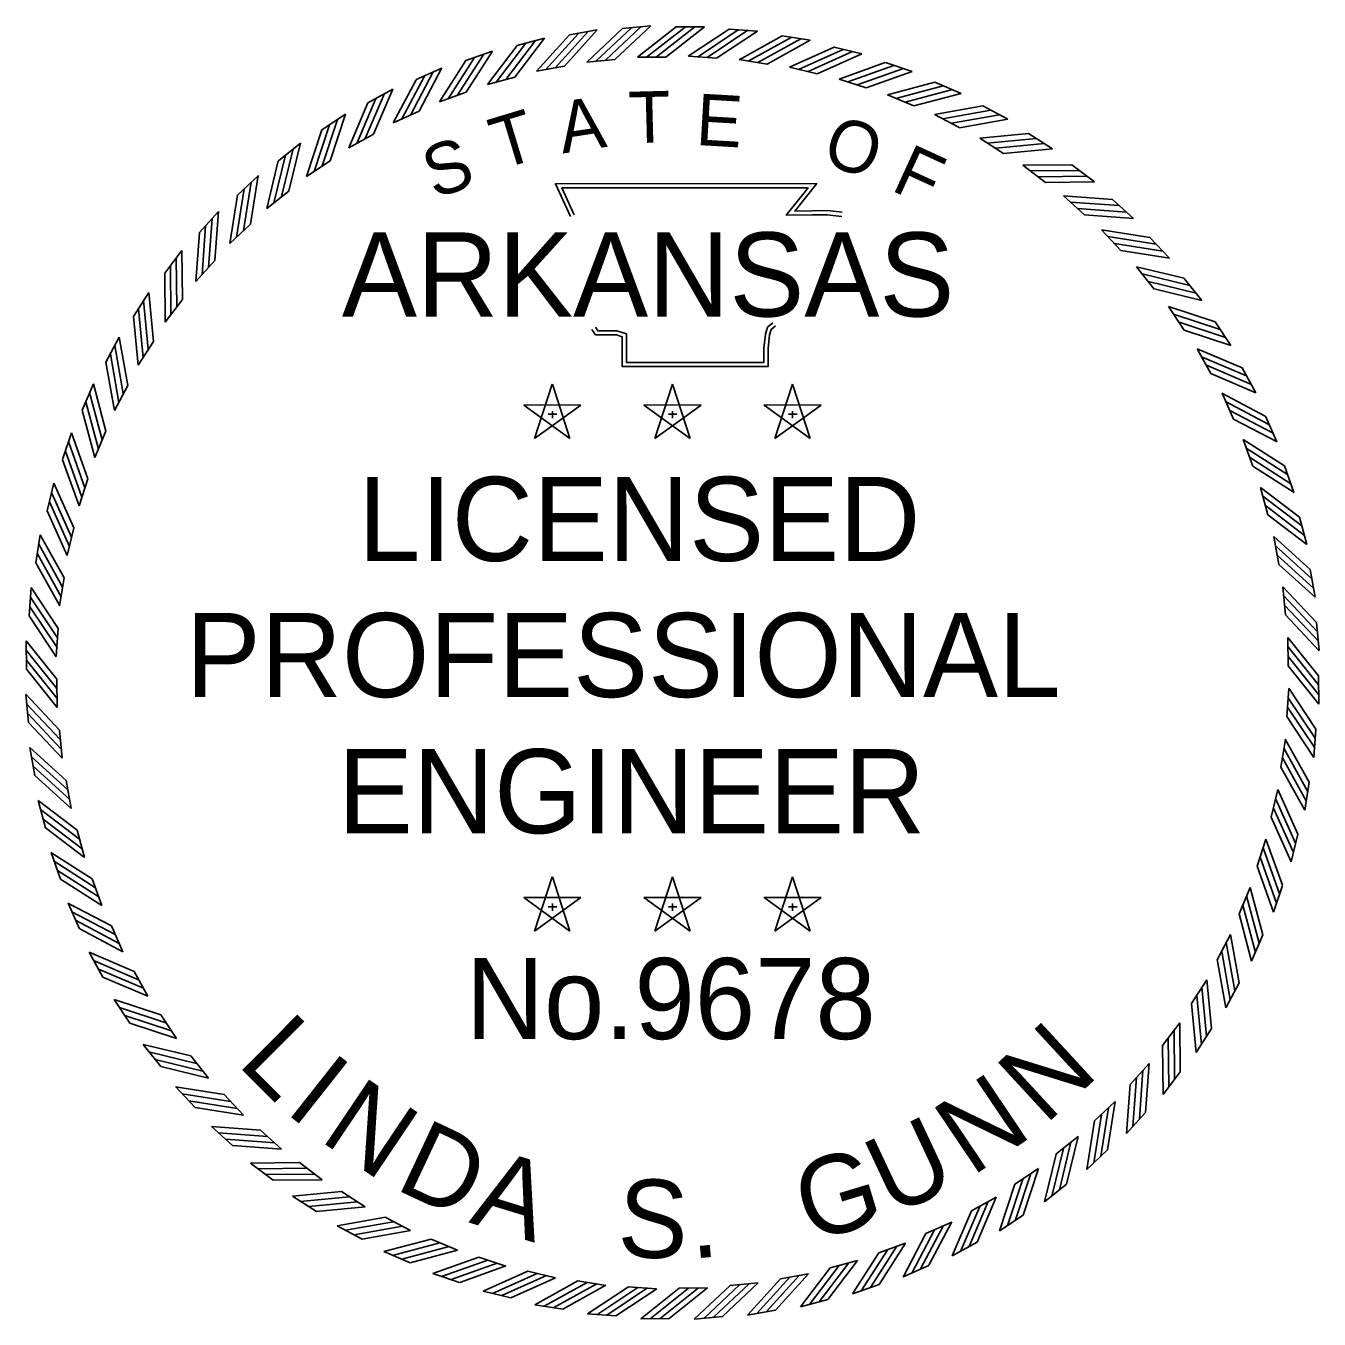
# Model space of a CAD drawing. Extents: x -160 to 6143532, y -375 to 762199.
# Drawn here: x 566 to 597.06, y -166.74 to -135.68 of the extents above; entities that cross this region are included whole.
import ezdxf

# ---------------------------------------------------------------- set-up
doc = ezdxf.new("R2010")
doc.units = 0
doc.layers.add('STAMP', color=7, linetype='Continuous')

msp = doc.modelspace()

# ---------------------------------------------------------------- linework, layer by layer
at = {"layer": 'STAMP'}
for p, q in [((580.329, -135.745), (581.006, -135.682)), ((581.617, -135.707), (582.297, -135.707)), ((577.8, -136.153), (578.458, -135.98)), ((579.056, -135.897), (579.726, -135.779)), ((582.891, -135.758), (583.569, -135.808)), ((584.162, -135.923), (584.834, -136.029)), ((576.57, -136.513), (577.211, -136.286)), ((585.415, -136.192), (586.076, -136.353)), ((579.471, -136.55), (580.15, -136.488)), ((580.689, -136.43), (581.37, -136.43)), ((581.912, -136.411), (582.592, -136.461)), ((583.133, -136.493), (583.806, -136.599)), ((586.642, -136.564), (587.288, -136.779)), ((575.373, -136.973), (575.993, -136.694)), ((577.087, -137.089), (577.746, -136.916)), ((578.268, -136.771), (578.939, -136.652)), ((584.343, -136.676), (585.005, -136.837)), ((574.218, -137.53), (574.813, -137.201)), ((585.533, -136.958), (586.18, -137.173)), ((587.834, -137.036), (588.459, -137.304)), ((575.936, -137.505), (576.578, -137.277)), ((586.696, -137.337), (587.323, -137.605)), ((573.114, -138.181), (573.68, -137.803)), ((574.823, -138.014), (575.445, -137.734)), ((587.824, -137.811), (588.427, -138.13)), ((588.983, -137.605), (589.584, -137.924)), ((572.067, -138.92), (572.599, -138.498)), ((573.756, -138.613), (574.353, -138.283)), ((588.909, -138.376), (589.483, -138.744)), ((590.081, -138.267), (590.654, -138.634)), ((572.743, -139.298), (573.31, -138.919)), ((589.944, -139.029), (590.485, -139.443)), ((591.121, -139.017), (591.661, -139.43)), ((571.084, -139.744), (571.58, -139.279)), ((571.789, -140.064), (572.323, -139.64)), ((590.921, -139.766), (591.426, -140.223)), ((592.095, -139.851), (592.599, -140.307)), ((570.173, -140.646), (570.629, -140.141)), ((570.902, -140.907), (571.399, -140.44)), ((591.834, -140.58), (592.3, -141.077)), ((592.996, -140.762), (593.462, -141.258)), ((569.339, -141.62), (569.752, -141.079)), ((570.088, -141.819), (570.545, -141.314)), ((592.676, -141.467), (593.1, -142.001)), ((593.82, -141.745), (594.243, -142.277)), ((568.589, -142.659), (568.956, -142.086)), ((569.351, -142.797), (569.765, -142.255)), ((593.443, -142.421), (593.821, -142.988)), ((594.56, -142.792), (594.937, -143.358)), ((567.927, -143.757), (568.245, -143.156)), ((568.698, -143.831), (569.066, -143.257)), ((594.128, -143.435), (594.458, -144.031)), ((595.21, -143.896), (595.539, -144.491)), ((567.358, -144.906), (567.626, -144.281)), ((568.133, -144.916), (568.452, -144.314)), ((578.645, -144.288), (578.219, -145.593)), ((579.069, -145.592), (578.646, -144.286)), ((581.53, -144.288), (581.104, -145.593)), ((581.954, -145.592), (581.531, -144.286)), ((584.415, -144.288), (583.989, -145.593)), ((584.838, -145.592), (584.415, -144.286)), ((594.727, -144.501), (595.006, -145.123)), ((579.331, -144.786), (577.958, -144.785)), ((577.959, -144.786), (579.069, -145.594)), ((578.221, -145.592), (579.333, -144.786)), ((578.547, -145.005), (578.751, -145.005)), ((578.646, -144.932), (578.646, -145.104)), ((582.216, -144.786), (580.843, -144.785)), ((580.844, -144.786), (581.954, -145.594)), ((581.106, -145.592), (582.217, -144.786)), ((581.432, -145.005), (581.636, -145.005)), ((581.531, -144.932), (581.531, -145.104)), ((585.1, -144.786), (583.727, -144.785)), ((583.729, -144.786), (584.839, -145.594)), ((583.991, -145.592), (585.102, -144.786)), ((584.317, -145.005), (584.521, -145.005)), ((584.416, -144.932), (584.416, -145.104)), ((595.767, -145.051), (596.046, -145.671)), ((566.886, -146.098), (567.101, -145.453)), ((567.659, -146.044), (567.927, -145.417)), ((595.236, -145.614), (595.463, -146.257)), ((596.227, -146.248), (596.454, -146.889)), ((567.28, -147.207), (567.495, -146.56)), ((566.514, -147.325), (566.675, -146.664)), ((595.651, -146.765), (595.824, -147.424)), ((596.587, -147.478), (596.76, -148.136)), ((566.998, -148.398), (567.159, -147.735)), ((566.245, -148.578), (566.35, -147.906)), ((595.97, -147.946), (596.088, -148.617)), ((596.843, -148.734), (596.962, -149.404)), ((566.815, -149.607), (566.921, -148.934)), ((566.08, -149.849), (566.13, -149.171)), ((596.19, -149.149), (596.252, -149.828)), ((566.733, -150.828), (566.783, -150.148)), ((596.996, -150.007), (597.058, -150.684)), ((566.02, -151.13), (566.014, -150.45)), ((596.31, -150.367), (596.316, -151.049)), ((566.752, -152.051), (566.746, -151.37)), ((597.042, -151.288), (597.048, -151.968)), ((566.067, -152.411), (566.004, -151.734)), ((596.329, -151.59), (596.279, -152.27)), ((566.872, -153.269), (566.81, -152.59)), ((596.982, -152.569), (596.933, -153.247)), ((566.219, -153.684), (566.101, -153.014)), ((596.247, -152.811), (596.141, -153.484)), ((567.093, -154.472), (566.974, -153.801)), ((596.064, -154.021), (595.903, -154.683)), ((596.817, -153.84), (596.712, -154.512)), ((566.475, -154.94), (566.302, -154.282)), ((567.411, -155.654), (567.238, -154.994)), ((595.782, -155.211), (595.567, -155.858)), ((596.548, -155.094), (596.387, -155.754)), ((566.835, -156.171), (566.608, -155.529)), ((567.827, -156.804), (567.599, -156.162)), ((578.645, -156.116), (578.219, -157.421)), ((579.069, -157.42), (578.646, -156.114)), ((581.53, -156.116), (581.104, -157.421)), ((581.954, -157.42), (581.531, -156.114)), ((584.415, -156.116), (583.989, -157.421)), ((584.838, -157.42), (584.415, -156.114)), ((595.403, -156.374), (595.135, -157.001)), ((596.176, -156.32), (595.961, -156.966)), ((567.295, -157.367), (567.016, -156.747)), ((579.331, -156.614), (577.958, -156.613)), ((577.959, -156.614), (579.069, -157.422)), ((578.221, -157.42), (579.333, -156.614)), ((578.646, -156.76), (578.646, -156.932)), ((582.216, -156.614), (580.843, -156.613)), ((580.844, -156.614), (581.954, -157.422)), ((581.106, -157.42), (582.217, -156.614)), ((581.531, -156.76), (581.531, -156.932)), ((585.1, -156.614), (583.727, -156.613)), ((583.729, -156.614), (584.839, -157.422)), ((583.991, -157.42), (585.102, -156.614)), ((584.416, -156.76), (584.416, -156.932)), ((578.547, -156.833), (578.751, -156.833)), ((581.432, -156.833), (581.636, -156.833)), ((584.317, -156.833), (584.521, -156.833)), ((568.335, -157.917), (568.056, -157.295)), ((594.929, -157.502), (594.61, -158.105)), ((595.704, -157.512), (595.436, -158.138)), ((567.852, -158.522), (567.523, -157.927)), ((568.934, -158.984), (568.604, -158.387)), ((594.364, -158.587), (593.996, -159.161)), ((595.135, -158.661), (594.817, -159.262)), ((568.503, -159.627), (568.125, -159.061)), ((569.619, -159.997), (569.241, -159.43)), ((593.711, -159.622), (593.297, -160.164)), ((594.473, -159.759), (594.106, -160.332)), ((569.242, -160.674), (568.82, -160.141)), ((570.386, -160.951), (569.962, -160.417)), ((592.975, -160.599), (592.517, -161.105)), ((593.723, -160.799), (593.31, -161.339)), ((570.066, -161.656), (569.601, -161.16)), ((571.228, -161.838), (570.762, -161.341)), ((592.16, -161.512), (591.663, -161.978)), ((592.889, -161.773), (592.433, -162.277)), ((570.968, -162.567), (570.463, -162.111)), ((572.141, -162.653), (571.636, -162.196)), ((591.273, -162.354), (590.739, -162.778)), ((591.978, -162.675), (591.482, -163.14)), ((571.942, -163.401), (571.401, -162.988)), ((573.118, -163.389), (572.577, -162.975)), ((590.319, -163.121), (589.752, -163.499)), ((590.996, -163.498), (590.463, -163.921)), ((572.981, -164.151), (572.408, -163.784)), ((574.153, -164.042), (573.579, -163.674)), ((589.306, -163.806), (588.709, -164.136)), ((589.948, -164.238), (589.383, -164.615)), ((574.079, -164.813), (573.478, -164.495)), ((575.238, -164.607), (574.635, -164.289)), ((588.239, -164.405), (587.617, -164.684)), ((576.366, -165.081), (575.739, -164.813)), ((588.844, -164.888), (588.249, -165.217)), ((575.228, -165.382), (574.603, -165.114)), ((587.126, -164.914), (586.484, -165.141)), ((577.529, -165.461), (576.882, -165.245)), ((585.975, -165.329), (585.316, -165.502)), ((587.689, -165.445), (587.069, -165.724)), ((576.42, -165.854), (575.775, -165.639)), ((578.72, -165.742), (578.057, -165.581)), ((579.929, -165.925), (579.256, -165.819)), ((584.794, -165.648), (584.123, -165.766)), ((577.647, -166.226), (576.986, -166.065)), ((581.15, -166.007), (580.47, -165.957)), ((582.373, -165.988), (581.692, -165.994)), ((583.591, -165.868), (582.912, -165.93)), ((586.493, -165.905), (585.851, -166.132)), ((578.9, -166.495), (578.228, -166.39)), ((585.262, -166.265), (584.604, -166.438)), ((580.171, -166.661), (579.493, -166.611)), ((581.452, -166.72), (580.772, -166.726)), ((582.733, -166.674), (582.056, -166.736)), ((584.006, -166.522), (583.336, -166.64))]:
    msp.add_line(p, q, dxfattribs=at)
for points in [[(579.923, -136.506), (580.781, -135.7)], [(580.149, -136.488), (581.007, -135.682)], [(580.688, -136.431), (581.616, -135.707)], [(580.907, -136.433), (581.835, -135.709)], [(581.143, -136.428), (582.071, -135.704)], [(581.37, -136.43), (582.298, -135.706)], [(577.745, -136.916), (578.458, -135.98)], [(578.267, -136.771), (579.055, -135.898)], [(578.483, -136.735), (579.271, -135.862)], [(578.715, -136.689), (579.503, -135.815)], [(578.938, -136.652), (579.726, -135.778)], [(579.471, -136.551), (580.328, -135.745)], [(579.689, -136.533), (580.546, -135.727)], [(581.911, -136.412), (582.89, -135.758)], [(582.129, -136.43), (583.108, -135.776)], [(582.365, -136.442), (583.344, -135.789)], [(582.591, -136.461), (583.57, -135.807)], [(583.132, -136.494), (584.161, -135.923)], [(583.348, -136.53), (584.377, -135.959)], [(583.582, -136.561), (584.611, -135.991)], [(576.578, -137.277), (577.211, -136.286)], [(577.086, -137.09), (577.799, -136.154)], [(577.298, -137.037), (578.011, -136.101)], [(577.525, -136.971), (578.239, -136.035)], [(583.805, -136.599), (584.835, -136.028)], [(584.342, -136.676), (585.414, -136.193)], [(584.554, -136.73), (585.627, -136.246)], [(584.785, -136.781), (585.857, -136.297)], [(575.935, -137.506), (576.569, -136.514)], [(576.142, -137.434), (576.776, -136.443)], [(576.363, -137.351), (576.997, -136.359)], [(585.004, -136.837), (586.077, -136.353)], [(585.532, -136.958), (586.641, -136.565)], [(585.739, -137.029), (586.848, -136.636)], [(575.023, -137.927), (575.573, -136.886)], [(575.237, -137.825), (575.786, -136.784)], [(575.444, -137.734), (575.994, -136.693)], [(585.965, -137.099), (587.074, -136.705)], [(586.179, -137.172), (587.288, -136.779)], [(574.352, -138.283), (574.814, -137.2)], [(574.823, -138.014), (575.372, -136.974)], [(586.695, -137.337), (587.833, -137.037)], [(586.896, -137.425), (588.034, -137.125)], [(587.115, -137.513), (588.253, -137.213)], [(573.756, -138.613), (574.218, -137.531)], [(573.949, -138.509), (574.41, -137.427)], [(574.153, -138.39), (574.614, -137.308)], [(587.323, -137.604), (588.46, -137.304)], [(573.309, -138.92), (573.68, -137.803)], [(587.823, -137.811), (588.982, -137.605)], [(588.016, -137.915), (589.174, -137.71)], [(588.227, -138.021), (589.386, -137.816)], [(572.742, -139.299), (573.113, -138.182)], [(572.926, -139.179), (573.296, -138.062)], [(573.119, -139.043), (573.49, -137.927)], [(588.426, -138.129), (589.585, -137.923)], [(572.322, -139.64), (572.6, -138.497)], [(588.908, -138.376), (590.08, -138.267)], [(589.091, -138.496), (590.263, -138.387)], [(571.962, -139.931), (572.239, -138.787)], [(572.143, -139.78), (572.421, -138.636)], [(589.293, -138.619), (590.465, -138.51)], [(589.483, -138.743), (590.655, -138.634)], [(571.789, -140.065), (572.066, -138.921)], [(589.943, -139.029), (591.119, -139.017)], [(571.232, -140.594), (571.414, -139.431)], [(571.398, -140.44), (571.58, -139.278)], [(590.115, -139.164), (591.292, -139.152)], [(590.306, -139.303), (591.483, -139.291)], [(590.485, -139.442), (591.662, -139.43)], [(570.902, -140.908), (571.084, -139.745)], [(571.063, -140.759), (571.245, -139.597)], [(579.083, -140.259), (578.721, -139.473), (584.993, -139.47), (584.469, -140.128), (584.895, -140.123), (585.251, -140.118), (585.606, -140.157)], [(579.173, -140.217), (578.876, -139.573), (584.787, -139.569), (584.261, -140.23), (584.896, -140.222), (585.246, -140.217), (585.596, -140.256)], [(590.92, -139.766), (592.093, -139.851)], [(591.081, -139.914), (592.254, -139.999)], [(570.39, -141.481), (570.476, -140.307)], [(570.544, -141.314), (570.629, -140.14)], [(591.26, -140.068), (592.433, -140.154)], [(591.426, -140.222), (592.6, -140.307)], [(570.088, -141.82), (570.173, -140.647)], [(570.236, -141.659), (570.321, -140.486)], [(591.833, -140.58), (592.995, -140.762)], [(591.981, -140.741), (593.144, -140.923)], [(592.146, -140.91), (593.309, -141.092)], [(569.625, -142.434), (569.613, -141.257)], [(569.764, -142.255), (569.752, -141.078)], [(592.3, -141.076), (593.462, -141.258)], [(569.486, -142.625), (569.474, -141.448)], [(592.675, -141.467), (593.819, -141.744)], [(569.351, -142.798), (569.339, -141.621)], [(592.81, -141.64), (593.953, -141.917)], [(592.961, -141.822), (594.104, -142.099)], [(569.065, -143.257), (568.956, -142.086)], [(593.1, -142), (594.243, -142.278)], [(568.818, -143.649), (568.709, -142.477)], [(568.941, -143.447), (568.832, -142.275)], [(593.442, -142.421), (594.558, -142.791)], [(568.698, -143.832), (568.589, -142.66)], [(583.942, -142.81), (583.81, -142.917), (583.764, -143.086), (583.727, -143.424), (583.727, -143.764), (580.424, -143.764), (580.424, -143.278), (580.424, -143.074), (580.198, -143.005), (579.739, -143.005), (579.68, -142.915)], [(593.561, -142.604), (594.678, -142.975)], [(593.697, -142.797), (594.814, -143.168)], [(568.451, -144.314), (568.245, -143.155)], [(584.004, -142.887), (583.898, -142.974), (583.862, -143.104), (583.827, -143.429), (583.827, -143.863), (580.325, -143.863), (580.325, -143.278), (580.325, -143.148), (580.183, -143.104), (579.685, -143.104), (579.597, -142.969)], [(593.821, -142.987), (594.938, -143.358)], [(568.343, -144.513), (568.137, -143.355)], [(594.127, -143.434), (595.209, -143.896)], [(568.133, -144.917), (567.927, -143.758)], [(568.237, -144.724), (568.032, -143.566)], [(594.231, -143.627), (595.313, -144.088)], [(594.35, -143.831), (595.432, -144.293)], [(594.458, -144.03), (595.54, -144.492)], [(567.926, -145.418), (567.626, -144.28)], [(567.747, -145.844), (567.447, -144.707)], [(567.835, -145.625), (567.535, -144.487)], [(594.726, -144.501), (595.766, -145.05)], [(594.814, -144.701), (595.854, -145.251)], [(567.659, -146.045), (567.359, -144.907)], [(594.915, -144.915), (595.956, -145.464)], [(595.006, -145.122), (596.047, -145.672)], [(567.494, -146.561), (567.101, -145.452)], [(595.235, -145.613), (596.226, -146.247)], [(567.351, -147.001), (566.958, -145.892)], [(567.421, -146.775), (567.027, -145.666)], [(595.306, -145.82), (596.297, -146.454)], [(567.28, -147.208), (566.887, -146.099)], [(595.389, -146.041), (596.381, -146.675)], [(595.463, -146.256), (596.455, -146.889)], [(567.103, -147.956), (566.619, -146.883)], [(567.158, -147.736), (566.675, -146.663)], [(595.65, -146.764), (596.586, -147.477)], [(567.052, -148.186), (566.568, -147.114)], [(595.704, -146.976), (596.64, -147.69)], [(566.998, -148.399), (566.515, -147.326)], [(595.769, -147.203), (596.705, -147.917)], [(595.824, -147.423), (596.76, -148.136)], [(566.883, -149.158), (566.313, -148.129)], [(566.921, -148.935), (566.35, -147.906)], [(595.969, -147.945), (596.843, -148.733)], [(566.852, -149.392), (566.281, -148.363)], [(596.005, -148.161), (596.879, -148.949)], [(596.051, -148.393), (596.925, -149.181)], [(566.816, -149.608), (566.245, -148.579)], [(596.088, -148.616), (596.962, -149.404)], [(566.783, -150.149), (566.129, -149.17)], [(596.189, -149.149), (596.995, -150.006)], [(596.207, -149.367), (597.013, -150.224)], [(566.752, -150.611), (566.098, -149.632)], [(566.764, -150.375), (566.11, -149.396)], [(596.234, -149.602), (597.04, -150.459)], [(566.734, -150.829), (566.08, -149.85)], [(596.253, -149.827), (597.058, -150.685)], [(566.746, -151.371), (566.013, -150.449)], [(596.309, -150.366), (597.041, -151.287)], [(596.309, -150.585), (597.041, -151.506)], [(566.746, -151.597), (566.013, -150.676)], [(566.753, -151.833), (566.021, -150.912)], [(596.317, -150.821), (597.049, -151.742)], [(566.753, -152.052), (566.021, -151.131)], [(596.317, -151.048), (597.049, -151.969)], [(566.809, -152.591), (566.004, -151.733)], [(596.31, -151.807), (596.964, -152.786)], [(596.328, -151.589), (596.982, -152.568)], [(566.828, -152.817), (566.022, -151.959)], [(596.298, -152.043), (596.952, -153.022)], [(566.855, -153.052), (566.049, -152.194)], [(566.873, -153.27), (566.067, -152.412)], [(596.279, -152.269), (596.933, -153.248)], [(566.974, -153.802), (566.1, -153.014)], [(596.21, -153.026), (596.781, -154.055)], [(596.246, -152.81), (596.817, -153.839)], [(567.011, -154.025), (566.137, -153.237)], [(596.179, -153.26), (596.749, -154.289)], [(567.057, -154.257), (566.183, -153.469)], [(567.093, -154.473), (566.219, -153.685)], [(596.141, -153.484), (596.712, -154.513)], [(596.064, -154.02), (596.548, -155.092)], [(567.238, -154.995), (566.302, -154.282)], [(596.01, -154.232), (596.494, -155.305)], [(567.293, -155.215), (566.357, -154.502)], [(595.959, -154.463), (596.443, -155.535)], [(567.358, -155.442), (566.422, -154.729)], [(567.412, -155.654), (566.476, -154.941)], [(595.904, -154.682), (596.387, -155.755)], [(595.782, -155.21), (596.176, -156.319)], [(567.599, -156.163), (566.607, -155.529)], [(595.711, -155.417), (596.104, -156.526)], [(567.673, -156.377), (566.681, -155.743)], [(595.568, -155.857), (595.961, -156.966)], [(595.641, -155.643), (596.035, -156.752)], [(567.756, -156.598), (566.765, -155.964)], [(567.827, -156.805), (566.836, -156.171)], [(595.403, -156.373), (595.704, -157.511)], [(568.056, -157.296), (567.015, -156.747)], [(595.227, -156.793), (595.528, -157.931)], [(595.315, -156.574), (595.616, -157.712)], [(568.147, -157.504), (567.106, -156.954)], [(595.136, -157.001), (595.436, -158.138)], [(568.248, -157.717), (567.208, -157.167)], [(568.336, -157.917), (567.296, -157.368)], [(594.825, -157.694), (595.031, -158.852)], [(594.929, -157.501), (595.135, -158.66)], [(568.604, -158.388), (567.522, -157.926)], [(594.719, -157.905), (594.925, -159.064)], [(568.712, -158.587), (567.63, -158.126)], [(568.831, -158.792), (567.749, -158.33)], [(594.611, -158.104), (594.817, -159.263)], [(568.935, -158.984), (567.853, -158.522)], [(594.364, -158.586), (594.473, -159.758)], [(594.121, -158.971), (594.23, -160.143)], [(594.244, -158.769), (594.353, -159.941)], [(569.241, -159.431), (568.125, -159.06)], [(569.365, -159.621), (568.249, -159.25)], [(593.997, -159.161), (594.106, -160.333)], [(569.501, -159.814), (568.384, -159.444)], [(593.711, -159.621), (593.723, -160.797)], [(569.62, -159.998), (568.504, -159.627)], [(593.576, -159.793), (593.588, -160.97)], [(569.962, -160.418), (568.819, -160.141)], [(593.298, -160.163), (593.31, -161.34)], [(593.437, -159.984), (593.449, -161.161)], [(570.102, -160.597), (568.958, -160.319)], [(570.252, -160.779), (569.109, -160.501)], [(570.387, -160.951), (569.243, -160.674)], [(592.826, -160.759), (592.741, -161.933)], [(592.975, -160.598), (592.889, -161.771)], [(570.762, -161.342), (569.6, -161.16)], [(592.518, -161.104), (592.433, -162.278)], [(592.672, -160.938), (592.587, -162.111)], [(570.916, -161.508), (569.753, -161.327)], [(571.081, -161.677), (569.919, -161.495)], [(571.229, -161.838), (570.067, -161.656)], [(591.999, -161.659), (591.817, -162.822)], [(592.16, -161.511), (591.978, -162.673)], [(591.664, -161.978), (591.482, -163.14)], [(591.83, -161.824), (591.649, -162.987)], [(571.636, -162.196), (570.462, -162.111)], [(571.803, -162.35), (570.629, -162.265)], [(591.273, -162.353), (590.996, -163.497)], [(571.981, -162.504), (570.808, -162.419)], [(572.142, -162.653), (570.969, -162.567)], [(590.919, -162.639), (590.641, -163.782)], [(591.1, -162.488), (590.823, -163.631)], [(572.577, -162.976), (571.4, -162.988)], [(590.74, -162.778), (590.463, -163.921)], [(572.756, -163.115), (571.579, -163.127)], [(572.947, -163.254), (571.77, -163.266)], [(590.136, -163.239), (589.766, -164.356)], [(590.32, -163.12), (589.949, -164.237)], [(573.119, -163.389), (571.943, -163.401)], [(589.753, -163.499), (589.382, -164.616)], [(589.943, -163.375), (589.572, -164.492)], [(573.579, -163.675), (572.408, -163.784)], [(573.769, -163.799), (572.597, -163.908)], [(573.971, -163.922), (572.799, -164.031)], [(589.114, -163.909), (588.652, -164.991)], [(589.306, -163.805), (588.844, -164.887)], [(574.154, -164.042), (572.982, -164.151)], [(588.71, -164.136), (588.248, -165.218)], [(588.909, -164.028), (588.448, -165.11)], [(574.636, -164.289), (573.477, -164.495)], [(574.835, -164.397), (573.676, -164.603)], [(575.046, -164.503), (573.888, -164.709)], [(588.039, -164.492), (587.489, -165.532)], [(588.239, -164.404), (587.69, -165.444)], [(575.239, -164.607), (574.08, -164.813)], [(575.74, -164.814), (574.602, -165.115)], [(587.618, -164.684), (587.069, -165.725)], [(587.826, -164.593), (587.276, -165.634)], [(575.947, -164.905), (574.809, -165.206)], [(576.166, -164.993), (575.029, -165.294)], [(576.367, -165.081), (575.229, -165.382)], [(586.485, -165.141), (585.851, -166.133)], [(586.699, -165.068), (586.065, -166.059)], [(586.92, -164.984), (586.286, -165.975)], [(587.127, -164.913), (586.493, -165.904)], [(576.883, -165.246), (575.774, -165.639)], [(577.097, -165.319), (575.988, -165.713)], [(577.323, -165.389), (576.214, -165.783)], [(577.53, -165.46), (576.421, -165.854)], [(585.317, -165.503), (584.604, -166.439)], [(585.537, -165.447), (584.823, -166.383)], [(585.764, -165.382), (585.051, -166.318)], [(585.976, -165.328), (585.263, -166.264)], [(578.058, -165.582), (576.985, -166.065)], [(578.278, -165.637), (577.205, -166.121)], [(578.508, -165.688), (577.436, -166.172)], [(578.721, -165.742), (577.648, -166.226)], [(579.257, -165.82), (578.227, -166.39)], [(584.124, -165.766), (583.336, -166.64)], [(584.347, -165.729), (583.559, -166.603)], [(584.579, -165.683), (583.791, -166.557)], [(584.795, -165.647), (584.007, -166.521)], [(579.48, -165.857), (578.451, -166.427)], [(579.714, -165.888), (578.685, -166.459)], [(579.93, -165.924), (578.901, -166.495)], [(580.471, -165.957), (579.492, -166.611)], [(580.697, -165.976), (579.718, -166.63)], [(580.933, -165.988), (579.954, -166.642)], [(581.151, -166.006), (580.172, -166.66)], [(581.692, -165.995), (580.771, -166.727)], [(581.919, -165.995), (580.998, -166.727)], [(582.155, -165.987), (581.234, -166.719)], [(582.374, -165.987), (581.453, -166.719)], [(582.913, -165.931), (582.055, -166.737)], [(583.139, -165.912), (582.281, -166.718)], [(583.373, -165.885), (582.516, -166.691)], [(583.592, -165.867), (582.734, -166.673)]]:
    msp.add_lwpolyline(points, dxfattribs=at)

# ---------------------------------------------------------------- texts
for s, height, rotation, p in [('T', 1.237, 1.4789, (580.49, -138.502)), ('A', 1.237, 8.6788, (578.892, -138.749)), ('E', 1.237, 356.672, (582.073, -138.54)), ('T', 1.237, 16.9015, (577.39, -139.141)), ('O', 1.237, 341.2218, (585.077, -138.964)), ('S', 1.237, 19.7726, (575.816, -139.847)), ('F', 1.237, 335.3628, (586.745, -139.616)), ('L', 1.879, 315.1295, (571.051, -160.61)), ('N', 1.879, 42.6817, (590.472, -162.096)), ('I', 1.879, 321.696, (572.193, -161.748)), ('N', 1.879, 326.0736, (573.024, -162.43)), ('N', 1.879, 33.9264, (588.712, -163.329)), ('D', 1.879, 334.8288, (574.83, -163.595)), ('U', 1.879, 25.1712, (586.785, -164.28)), ('G', 1.879, 16.7808, (584.823, -164.907)), ('A', 1.879, 342.8544, (576.624, -164.411)), ('S', 1.879, 357.8112, (580.195, -165.232)), ('.', 1.879, 5.1072, (581.986, -165.288))]:
    msp.add_text(s, height=height, rotation=rotation, dxfattribs=at).set_placement(p)
for s, height, p in [('ARKANSAS', 2.0193, (573.593, -142.661)), ('LICENSED', 2.0193, (573.978, -148.531)), ('PROFESSIONAL', 2.01933, (569.843, -151.8)), ('ENGINEER', 2.0193, (573.497, -155.069)), ('No.9678', 1.9472, (576.566, -160.012))]:
    msp.add_text(s, height=height, dxfattribs=at).set_placement(p)

doc.saveas('drawing.dxf')
